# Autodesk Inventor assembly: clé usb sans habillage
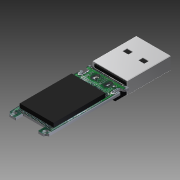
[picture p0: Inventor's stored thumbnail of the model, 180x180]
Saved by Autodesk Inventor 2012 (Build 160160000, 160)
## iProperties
Created: 2013-04
Part Number: clé usb sans habillage
Document SubType Name: Assembly
Designer: hilarion
Author: hilarion
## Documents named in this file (4)
- D:\dominique\travail\année 2012-2013\cit\prépa projet\clé usb sans habillage.iam
- D:\dominique\travail\année 2012-2013\cit\prépa projet\usb gris.ipt
- D:\dominique\travail\année 2012-2013\cit\prépa projet\usb noir.ipt
- D:\dominique\travail\année 2012-2013\cit\prépa projet\carte.ipt
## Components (3 placed, 3 different names)
1. usb gris:1 — Affleurement:1, Placage:1, Placage:2
2. usb noir:1 — Affleurement:1, Placage:1, Placage:2, Affleurement:2
3. carte:1 — Affleurement:2
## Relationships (4: Flush 2, Mate 2)
- Affleurement:1 [Flush]: usb gris:1 ↔ usb noir:1
- Placage:1 [Mate]: usb gris:1 ↔ usb noir:1
- Placage:2 [Mate]: usb gris:1 ↔ usb noir:1
- Affleurement:2 [Flush]: usb noir:1 ↔ carte:1
